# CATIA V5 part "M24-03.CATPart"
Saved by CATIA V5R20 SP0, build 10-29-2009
Part number: M24-03
Revision: ANY
Definition: UNKNOWN
Nomenclature: M24-03
Source: Unknown
Bounding box of the stored display mesh (mm): x 0 to 50, y -22.5 to 22.5, z 0 to 20
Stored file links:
  C:\Users\Utente\Desktop\IO LAVORO\3D X SITO CF\X 3D SITO CF 27-09-2020\740T\740T-24\M24-03.CATPart
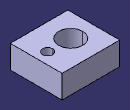
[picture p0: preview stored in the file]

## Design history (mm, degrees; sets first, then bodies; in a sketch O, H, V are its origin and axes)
Body1 "NONE" (main body)
  Solid1: solid without history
